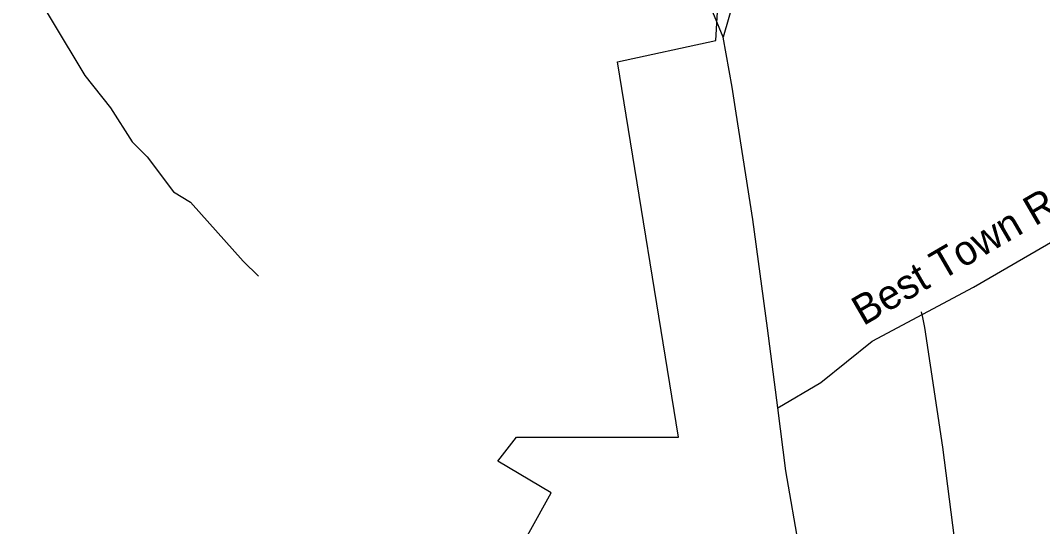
# Model space of a CAD drawing. Extents: x 1268485 to 1426702, y 514839 to 616766.
# Drawn here: x 1315979 to 1318241, y 570783 to 571902 of the extents above; entities that cross this region are included whole.
import ezdxf

# ---------------------------------------------------------------- set-up
doc = ezdxf.new("R2010")
doc.units = 0
for name, color, linetype in [('Old_Level_11', 7, 'Continuous'), ('Old_Level_29', 7, 'Continuous'), ('Old_Level_32', 7, 'Continuous'), ('Old_Level_35', 7, 'Continuous'), ('Old_Level_48', 7, 'Continuous'), ('Old_Level_49', 7, 'Continuous'), ('Old_Level_62', 7, 'Continuous')]:
    doc.layers.add(name, color=color, linetype=linetype)

msp = doc.modelspace()

# ---------------------------------------------------------------- linework, layer by layer
at = {"layer": 'Old_Level_29'}
for points in [[(1317534.533, 571865.437), (1317483.269, 571988.969)], [(1317655.393, 571045.728), (1317632.02, 571221.412), (1317599.903, 571461.591), (1317562.716, 571697.372), (1317554.263, 571754.879), (1317534.533, 571865.437)], [(1317699.626, 570312.51), (1317713.157, 570408.189), (1317716.538, 570507.981), (1317703.016, 570731.923), (1317672.589, 570905.967), (1317655.393, 571045.728)]]:
    msp.add_lwpolyline(points, dxfattribs=at)
at = {"layer": 'Old_Level_32'}
for points in [[(1317557.644, 571946.684), (1317534.533, 571865.437)], [(1317655.393, 571045.728), (1317750.346, 571101.323), (1317863.599, 571192.659), (1318088.207, 571312.001), (1318323.48, 571448.737), (1318419.052, 571514.447), (1318463.231, 571555.02), (1318470.224, 571561.442), (1318529.957, 571636.078), (1318631.984, 571803.708), (1318653.959, 571891.309)]]:
    msp.add_lwpolyline(points, dxfattribs=at)
at = {"layer": 'Old_Level_35'}
msp.add_lwpolyline([(1317972.369, 571257.419), (1317975.239, 571245.014), (1317979.751, 571223.226), (1318019.531, 570958.709), (1318056.03, 570670.868), (1318055.21, 570652.618), (1318052.852, 570639.238), (1318049.878, 570629.293), (1318045.47, 570616.17), (1318039.216, 570606.687), (1318028.245, 570592.076), (1317985.082, 570538.045), (1317951.658, 570498.214), (1317933.614, 570480.887), (1317920.798, 570470.173), (1317906.137, 570460.689), (1317891.476, 570455.101), (1317869.125, 570449.001), (1317850.158, 570445.361), (1317833.856, 570443.208), (1317804.841, 570445.106), (1317723.64, 570450.232), (1317711.747, 570450.385)], dxfattribs=at)
at = {"layer": 'Old_Level_48'}
msp.add_lwpolyline([(1317458.977, 569297.869), (1317423.711, 569409.67), (1317312.034, 569380.249), (1317323.789, 570139.31), (1316835.936, 570139.31), (1316718.381, 570056.93), (1316653.725, 570156.962), (1316706.626, 570298.183), (1316583.192, 570362.909), (1316818.303, 570627.699), (1317000.513, 570580.625), (1317153.334, 570857.182), (1317035.779, 570927.792), (1317076.923, 570980.75), (1317435.466, 570980.75), (1317300.278, 571810.422), (1317517.755, 571857.495), (1317540.243, 572240.856), (1317502.163, 572397.547), (1317404.848, 572554.238), (1317966.781, 572913.863), (1318650.413, 573499.692)], dxfattribs=at)
at = {"layer": 'Old_Level_49'}
msp.add_lwpolyline([(1317458.977, 569297.869), (1317423.711, 569409.67), (1317312.034, 569380.249), (1317323.789, 570139.31), (1316835.936, 570139.31), (1316718.381, 570056.93), (1316653.725, 570156.962), (1316706.626, 570298.183), (1316583.192, 570362.909), (1316818.303, 570627.699), (1317000.513, 570580.625), (1317153.334, 570857.182), (1317035.779, 570927.792), (1317076.923, 570980.75), (1317435.466, 570980.75), (1317300.278, 571810.422), (1317517.755, 571857.495), (1317540.243, 572240.856), (1317502.163, 572397.547), (1317404.848, 572554.238), (1317966.781, 572913.863), (1318650.413, 573499.692)], dxfattribs=at)
at = {"layer": 'Old_Level_62'}
msp.add_lwpolyline([(1315979.262, 572017.547), (1316121.774, 571780.148), (1316178.163, 571708.739), (1316226.555, 571633.536), (1316259.774, 571600.83), (1316318.008, 571523.423), (1316355.43, 571500.509), (1316472.413, 571369.685), (1316505.734, 571336.928)], dxfattribs=at)

# ---------------------------------------------------------------- texts
at = {"layer": 'Old_Level_11'}
msp.add_text('Best Town Rd.', height=65.61666, rotation=30.164361, dxfattribs=at).set_placement((1317844.01, 571225.652))

doc.saveas('drawing.dxf')
